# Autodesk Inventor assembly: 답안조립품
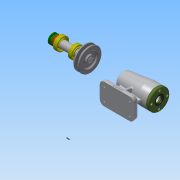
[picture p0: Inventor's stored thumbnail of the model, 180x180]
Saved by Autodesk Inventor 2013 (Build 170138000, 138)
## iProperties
Created: 2017-01
Part Number: 답안조립품
Document SubType Name: Assembly
Designer: Administrator
Author: Administrator
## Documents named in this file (12)
- C:\Users\Administrator\Desktop\470108V1009\답안조립품.iam
- C:\Users\Administrator\Desktop\470108V1009\V벨트풀리.ipt
- C:\Users\Administrator\Desktop\470108V1009\멈춤나사 M3x8.ipt
- C:\Users\Administrator\Desktop\470108V1009\베어링 6004.ipt
- C:\Users\Administrator\Desktop\470108V1009\베어링 51202.ipt
- C:\Users\Administrator\Desktop\470108V1009\본체.ipt
- C:\Users\Administrator\Desktop\470108V1009\볼트 M4 x 12.ipt
- C:\Users\Administrator\Desktop\470108V1009\어댑터슬리브.ipt
- C:\Users\Administrator\Desktop\470108V1009\오일 실.ipt
- C:\Users\Administrator\Desktop\470108V1009\축.ipt
- C:\Users\Administrator\Desktop\470108V1009\커버.ipt
- C:\Users\Administrator\Desktop\470108V1009\키 5 x 5 x 16.ipt
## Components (6 placed, 2 different names)
1. ISO 4762 M4 x 12:5 — 플러쉬:1
2. V벨트풀리:1 — 플러쉬:2
3. ISO 4762 M4 x 12:1
4. ISO 4762 M4 x 12:2
5. ISO 4762 M4 x 12:3
6. ISO 4762 M4 x 12:4
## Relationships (2: Flush 2)
- 플러쉬:1 [Flush]: ISO 4762 M4 x 12:5
- 플러쉬:2 [Flush]: V벨트풀리:1
